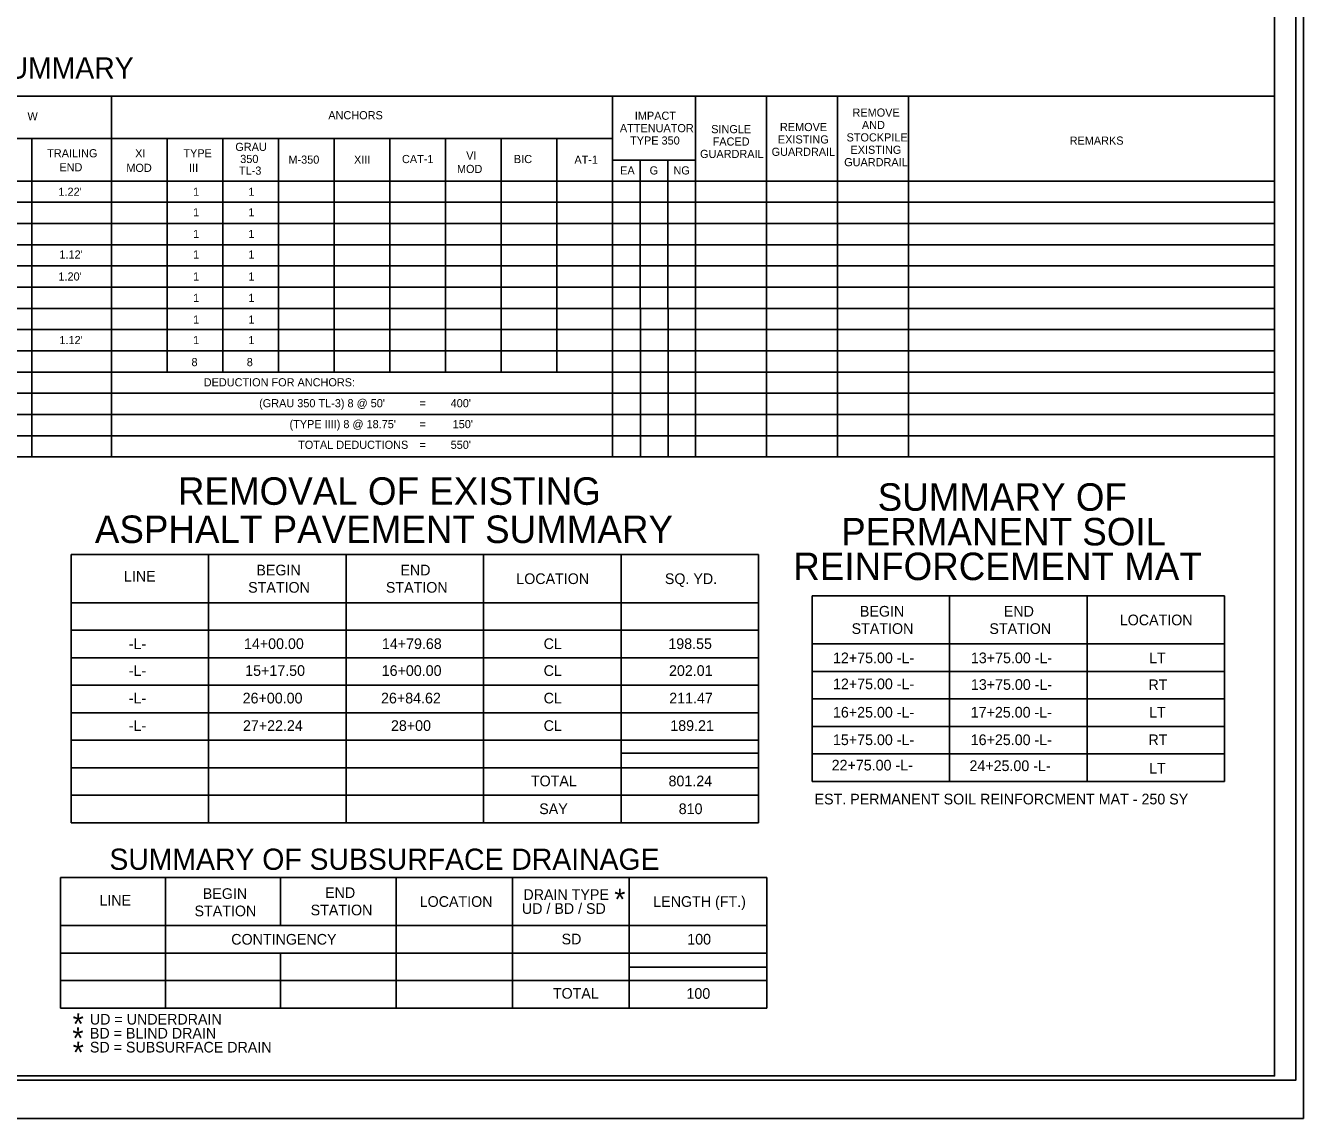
# Model space of a CAD drawing. Extents: x 573976 to 575684, y -54210 to -51535.
# Drawn here: x 574907 to 575660, y -52822 to -52178 of the extents above; entities that cross this region are included whole.
import ezdxf

# ---------------------------------------------------------------- set-up
doc = ezdxf.new("R2010")
doc.units = 0
for name, color, linetype in [('Sheet Cutting Line CELL', 7, 'Continuous'), ('Sheet Pipe Summary Grid CELL', 7, 'Continuous'), ('Sheet Plot Border Inside CELL', 7, 'Continuous'), ('Sheet Plot Border Outside CELL', 7, 'Continuous'), ('Sheet Summary Combination CELL', 7, 'Continuous'), ('Sheet Summary Combination Grid CELL', 7, 'Continuous'), ('Sheet Summary Earthwork CELL', 7, 'Continuous')]:
    doc.layers.add(name, color=color, linetype=linetype)

msp = doc.modelspace()

# ---------------------------------------------------------------- linework, layer by layer
at = {"layer": 'Sheet Cutting Line CELL'}
msp.add_line((573976.22, -52822.05), (575660.22, -52822.05), dxfattribs=at)
at = {"layer": 'Sheet Pipe Summary Grid CELL'}
for p, q in [((575643.22, -52369.95), (574143.22, -52369.95)), ((575643.22, -52432.45), (574143.22, -52432.45))]:
    msp.add_line(p, q, dxfattribs=at)
at = {"layer": 'Sheet Plot Border Inside CELL'}
msp.add_lwpolyline([(575655.72, -51744.5), (573989.22, -51744.5), (573989.22, -52799.6), (575655.72, -52799.6)], close=True, dxfattribs=at)
at = {"layer": 'Sheet Plot Border Outside CELL'}
msp.add_lwpolyline([(575660.22, -51722.05), (573976.22, -51722.05), (573976.22, -52822.05), (575660.22, -52822.05)], close=True, dxfattribs=at)
at = {"layer": 'Sheet Summary Combination CELL'}
for p, q in [((575258.14, -52606.96), (575339.14, -52606.96)), ((575262.97, -52732.95), (575343.97, -52732.95))]:
    msp.add_line(p, q, dxfattribs=at)
msp.add_lwpolyline([(575643.22, -51747.05), (574143.22, -51747.05), (574143.22, -52797.05), (575643.22, -52797.05)], close=True, dxfattribs=at)
at = {"layer": 'Sheet Summary Combination Grid CELL'}
for p, q in [((574143.22, -52219.95), (575643.22, -52219.95)), ((574957.87, -52219.95), (574957.87, -52432.45)), ((575253.17, -52219.95), (575253.17, -52432.45)), ((575302.02, -52219.95), (575302.02, -52432.45)), ((575343.82, -52219.95), (575343.82, -52432.45)), ((575385.62, -52219.95), (575385.62, -52432.45)), ((575427.47, -52219.95), (575427.47, -52432.45)), ((575253.17, -52244.95), (574776.02, -52244.95)), ((574910.97, -52244.95), (574910.97, -52432.45)), ((574990.67, -52244.95), (574990.67, -52382.45)), ((575023.47, -52244.95), (575023.47, -52382.45)), ((575056.32, -52244.95), (575056.32, -52382.45)), ((575089.12, -52244.95), (575089.12, -52382.45)), ((575121.92, -52244.95), (575121.92, -52382.45)), ((575154.72, -52244.95), (575154.72, -52382.45)), ((575187.57, -52244.95), (575187.57, -52382.45)), ((575220.37, -52244.95), (575220.37, -52382.45)), ((575253.17, -52257.7), (575301.77, -52257.7)), ((575269.43, -52257.7), (575269.53, -52432.45)), ((575285.78, -52257.7), (575285.88, -52432.45)), ((574143.22, -52269.95), (575643.22, -52269.95)), ((574143.22, -52282.45), (575643.22, -52282.45)), ((574143.22, -52294.95), (575643.22, -52294.95)), ((574143.22, -52307.45), (575643.22, -52307.45)), ((574143.22, -52319.95), (575643.22, -52319.95)), ((574143.22, -52332.45), (575643.22, -52332.45)), ((574143.22, -52344.95), (575643.22, -52344.95)), ((574143.22, -52357.45), (575643.22, -52357.45)), ((574143.22, -52369.95), (575643.22, -52369.95)), ((574143.22, -52382.45), (575643.22, -52382.45)), ((574143.22, -52394.95), (575643.22, -52394.95)), ((574143.22, -52407.45), (575643.22, -52407.45)), ((574143.22, -52419.95), (575643.22, -52419.95)), ((574143.22, -52432.45), (575643.22, -52432.45))]:
    msp.add_line(p, q, dxfattribs=at)
at = {"layer": 'Sheet Summary Earthwork CELL'}
for p, q in [((574934.14, -52647.93), (574934.14, -52489.98)), ((574934.14, -52489.98), (575015.14, -52489.98)), ((574934.14, -52489.98), (575339.14, -52489.98)), ((575015.14, -52489.98), (575015.14, -52647.93)), ((575096.14, -52647.93), (575096.14, -52489.98)), ((575096.14, -52489.98), (575177.14, -52489.98)), ((575177.14, -52489.98), (575177.14, -52647.93)), ((575258.14, -52647.93), (575258.14, -52489.98)), ((575258.14, -52489.98), (575339.14, -52489.98)), ((575339.14, -52489.98), (575339.14, -52647.93)), ((575370.71, -52514.26), (575370.71, -52623.61)), ((575370.71, -52514.26), (575613.71, -52514.26)), ((575451.71, -52623.61), (575451.71, -52514.26)), ((575451.71, -52514.26), (575532.71, -52514.26)), ((575532.71, -52514.26), (575532.71, -52623.61)), ((575613.71, -52623.61), (575613.71, -52514.26)), ((575339.14, -52518.33), (574934.14, -52518.33)), ((574934.14, -52534.53), (575339.14, -52534.53)), ((575339.14, -52534.53), (575339.14, -52550.73)), ((575613.71, -52542.61), (575370.71, -52542.61)), ((574934.14, -52550.73), (575339.14, -52550.73)), ((575370.71, -52558.81), (575613.71, -52558.81)), ((575339.14, -52566.93), (574934.14, -52566.93)), ((575339.14, -52566.93), (574934.14, -52566.93)), ((575370.71, -52575.01), (575613.71, -52575.01)), ((574934.14, -52583.13), (575339.14, -52583.13)), ((574934.14, -52583.13), (575339.14, -52583.13)), ((575613.71, -52591.21), (575370.71, -52591.21)), ((575339.14, -52599.33), (574934.14, -52599.33)), ((575370.71, -52607.41), (575613.71, -52607.41)), ((575339.14, -52615.53), (574934.14, -52615.53)), ((575613.71, -52623.61), (575370.71, -52623.61)), ((575339.14, -52631.73), (574934.14, -52631.73)), ((574934.14, -52647.93), (575339.14, -52647.93)), ((575339.14, -52647.93), (574934.14, -52647.93)), ((574927.9, -52757.07), (574927.9, -52680.12)), ((574927.9, -52680.12), (575008.9, -52680.12)), ((574927.9, -52680.12), (575275.27, -52680.12)), ((574989.81, -52680.12), (574989.81, -52757.07)), ((575057.41, -52680.12), (575138.41, -52680.12)), ((575057.41, -52708.47), (575057.41, -52680.12)), ((575125.57, -52680.12), (575125.57, -52757.07)), ((575194.27, -52680.12), (575194.27, -52757.07)), ((575262.97, -52757.07), (575262.97, -52680.12)), ((575262.97, -52680.12), (575343.97, -52680.12)), ((575262.97, -52680.12), (575262.97, -52757.07)), ((575343.97, -52680.12), (575343.97, -52757.07)), ((575343.97, -52708.47), (574927.9, -52708.47)), ((574927.9, -52724.67), (575343.97, -52724.67)), ((575057.41, -52757.07), (575057.41, -52724.67)), ((575343.97, -52724.67), (575343.97, -52740.87)), ((574927.9, -52740.87), (575343.97, -52740.87)), ((575343.97, -52757.07), (574927.9, -52757.07)), ((575343.97, -52757.07), (574927.9, -52757.07))]:
    msp.add_line(p, q, dxfattribs=at)

# ---------------------------------------------------------------- texts
at = {"layer": 'Sheet Summary Combination CELL'}
for s, height, p in [('GUARDRAIL SUMMARY', 12.5001, (574783.37, -52209.65)), ('W', 4.8, (574908.42, -52234.25)), ('ANCHORS', 4.8, (575085.67, -52233.6)), ('IMPACT', 4.8, (575266.27, -52233.9)), ('REMOVE', 4.8, (575394.52, -52232.05)), ('ATTENUATOR', 4.8, (575257.47, -52241.2)), ('SINGLE', 4.8, (575311.27, -52241.8)), ('REMOVE', 4.8, (575351.77, -52240.55)), ('AND', 4.8, (575400.07, -52239.35)), ('TYPE 350', 4.8, (575263.47, -52248.5)), ('FACED', 4.8, (575312.12, -52249.1)), ('EXISTING', 4.8, (575350.57, -52247.85)), ('STOCKPILE', 4.8, (575391.02, -52246.65)), ('REMARKS', 4.8, (575522.47, -52248.55)), ('TRAILING', 4.8, (574920.02, -52256)), ('XI', 4.8, (574971.87, -52256.05)), ('TYPE', 4.8, (575000.28, -52256)), ('GRAU', 4.8, (575030.87, -52252.26)), ('VI', 4.8, (575166.92, -52257.35)), ('GUARDRAIL', 4.8, (575304.72, -52256.4)), ('GUARDRAIL', 4.8, (575346.87, -52255.15)), ('EXISTING', 4.8, (575393.32, -52253.95)), ('END', 4.8, (574927.22, -52264.25)), ('MOD', 4.8, (574966.67, -52264.6)), ('III', 4.8, (575003.64, -52264.55)), ('TL-3', 4.8, (575033.03, -52266.22)), ('350', 4.8, (575033.78, -52259.35)), ('M-350', 4.8, (575062.17, -52259.75)), ('XIII', 4.8, (575100.82, -52259.75)), ('CAT-1', 4.8, (575129.07, -52259.4)), ('MOD', 4.8, (575161.47, -52265.25)), ('BIC', 4.8, (575195.02, -52259.4)), ('AT-1', 4.8, (575230.67, -52259.8)), ('EA', 4.8, (575257.62, -52266.1)), ('G', 4.8, (575274.97, -52266.1)), ('NG', 4.8, (575289.02, -52266.1)), ('GUARDRAIL', 4.8, (575389.62, -52261.25)), ("1.22'", 4.8, (574926.65, -52278.67)), ('1', 4.8, (575006, -52278.67)), ('1', 4.8, (575038.57, -52278.67)), ('1', 4.8, (575006, -52290.76)), ('1', 4.8, (575038.57, -52290.76)), ('1', 4.8, (575006, -52303.53)), ('1', 4.8, (575038.57, -52303.53)), ("1.12'", 4.8, (574927.23, -52315.62)), ('1', 4.8, (575006, -52315.62)), ('1', 4.8, (575038.57, -52315.62)), ("1.20'", 4.8, (574926.65, -52328.58)), ('1', 4.8, (575006, -52328.58)), ('1', 4.8, (575038.57, -52328.58)), ('1', 4.8, (575006, -52341.17)), ('1', 4.8, (575038.57, -52341.17)), ('1', 4.8, (575006, -52353.95)), ('1', 4.8, (575038.57, -52353.95)), ("1.12'", 4.8, (574927.23, -52366.03)), ('1', 4.8, (575006, -52366.03)), ('1', 4.8, (575038.57, -52366.03)), ('8', 4.8, (575005.05, -52379.01)), ('8', 4.8, (575037.62, -52379.01)), ('DEDUCTION FOR ANCHORS:', 4.8, (575012.26, -52390.9)), ("(GRAU 350 TL-3) 8 @ 50'", 4.8, (575044.91, -52403.21)), ('=', 4.8, (575139.41, -52403.21)), ("400' ", 4.8, (575157.76, -52403.21)), ("(TYPE IIII) 8 @ 18.75'", 4.8, (575062.81, -52415.52)), ("150'", 4.8, (575158.94, -52415.52)), ('=', 4.8, (575139.41, -52415.52)), ('TOTAL DEDUCTIONS', 4.8, (575067.88, -52427.69)), ('=', 4.8, (575139.41, -52427.69)), ("550'", 4.8, (575157.76, -52427.69)), ('*', 12.55, (575254.17, -52699.26)), ('*', 12.55, (574935.06, -52772.66)), ('*', 12.55, (574934.9, -52781.01)), ('*', 12.55, (574935.06, -52789.4))]:
    msp.add_text(s, height=height, dxfattribs=at).set_placement(p)
at = {"layer": 'Sheet Summary Earthwork CELL'}
for s, height, p in [('REMOVAL OF EXISTING', 16.1999, (574997.06, -52460.66)), ('SUMMARY OF', 16.2, (575409.37, -52464.16)), ('ASPHALT PAVEMENT SUMMARY', 16.1999, (574948.12, -52483.16)), ('PERMANENT SOIL', 16.1999, (575387.86, -52484.57)), ('REINFORCEMENT MAT', 16.1999, (575359.65, -52505.01)), ('LINE', 6.277, (574965.27, -52505.84)), ('BEGIN', 6.277, (575043.3, -52502.22)), ('END', 6.277, (575128.13, -52502.22)), ('LOCATION', 6.277, (575196.44, -52507.32)), ('SQ. YD.', 6.277, (575283.99, -52507.32)), ('STATION', 6.277, (575038.44, -52512.42)), ('STATION', 6.277, (575119.6, -52512.42)), ('BEGIN', 6.277, (575398.88, -52526.5)), ('END', 6.277, (575483.7, -52526.5)), ('STATION', 6.277, (575394.01, -52536.7)), ('STATION', 6.277, (575475.17, -52536.7)), ('LOCATION', 6.277, (575552.01, -52531.6)), ('-L-', 6.277, (574968.14, -52545.6)), ('14+00.00', 6.277, (575035.98, -52545.6)), ('14+79.68', 6.277, (575117.26, -52545.6)), ('CL', 6.277, (575212.55, -52545.6)), ('198.55', 6.277, (575286.02, -52545.6)), ('12+75.00 -L-', 6.2774, (575383.03, -52553.94)), ('13+75.00 -L-', 6.2774, (575464.3, -52553.94)), ('-L-', 6.277, (574968.11, -52561.43)), ('15+17.50', 6.277, (575036.71, -52561.43)), ('16+00.00', 6.277, (575117.14, -52561.43)), ('CL', 6.277, (575212.55, -52561.43)), ('202.01', 6.277, (575286.41, -52561.43)), ('LT', 6.277, (575569.27, -52553.94)), ('12+75.00 -L-', 6.2774, (575383.03, -52569.27)), ('13+75.00 -L-', 6.2774, (575464.3, -52569.64)), ('RT', 6.277, (575568.89, -52569.77)), ('-L-', 6.277, (574968.11, -52577.63)), ('26+00.00', 6.277, (575035.21, -52577.63)), ('26+84.62', 6.277, (575116.73, -52577.63)), ('CL', 6.277, (575212.55, -52577.63)), ('211.47', 6.277, (575286.53, -52577.63)), ('16+25.00 -L-', 6.2774, (575383.01, -52585.97)), ('17+25.00 -L-', 6.2774, (575464.19, -52585.97)), ('LT', 6.277, (575569.27, -52585.97)), ('-L-', 6.277, (574968.11, -52593.83)), ('27+22.24', 6.277, (575035.38, -52593.83)), ('28+00', 6.277, (575122.59, -52593.83)), ('CL', 6.277, (575212.55, -52593.83)), ('189.21', 6.277, (575287.17, -52593.83)), ('15+75.00 -L-', 6.2774, (575383.01, -52602.17)), ('16+25.00 -L-', 6.2774, (575464.19, -52602.17)), ('RT', 6.277, (575568.89, -52602.17)), ('22+75.00 -L-', 6.2774, (575382.25, -52617.13)), ('24+25.00 -L-', 6.2774, (575463.44, -52617.47)), ('LT', 6.277, (575569.27, -52618.93)), ('TOTAL', 6.277, (575205.03, -52626.44)), ('801.24', 6.277, (575286.14, -52626.44)), ('SAY', 6.277, (575209.95, -52642.83)), ('810', 6.277, (575292.13, -52642.83)), ('EST. PERMANENT SOIL REINFORCMENT MAT - 250 SY', 6.2774, (575372.19, -52637.1)), ('SUMMARY OF SUBSURFACE DRAINAGE', 12.5001, (574956.68, -52675.64)), ('LINE', 6.277, (574950.79, -52696.68)), ('BEGIN', 6.277, (575011.71, -52692.77)), ('END', 6.277, (575083.8, -52692.23)), ('DRAIN TYPE ', 6.2774, (575200.62, -52693.34)), ('STATION', 6.277, (575006.85, -52702.97)), ('STATION', 6.277, (575075.27, -52702.43)), ('LOCATION', 6.277, (575139.51, -52697.45)), ('UD / BD / SD', 6.2774, (575199.74, -52701.57)), ('LENGTH (FT.)', 6.2774, (575277.15, -52697.45)), ('CONTINGENCY', 6.2774, (575028.48, -52719.68)), ('100', 6.277, (575297.17, -52719.64)), ('TOTAL', 6.277, (575217.98, -52751.52)), ('100', 6.277, (575296.69, -52751.6)), ('UD = UNDERDRAIN', 6.2774, (574945.2, -52766.77)), ('BD = BLIND DRAIN', 6.2774, (574945.2, -52775)), ('SD = SUBSURFACE DRAIN', 6.2774, (574945.2, -52783.22))]:
    msp.add_text(s, height=height, rotation=360, dxfattribs=at).set_placement(p)
msp.add_text('SD', height=6.277, dxfattribs=at).set_placement((575223.13, -52719.53))

doc.saveas('drawing.dxf')
